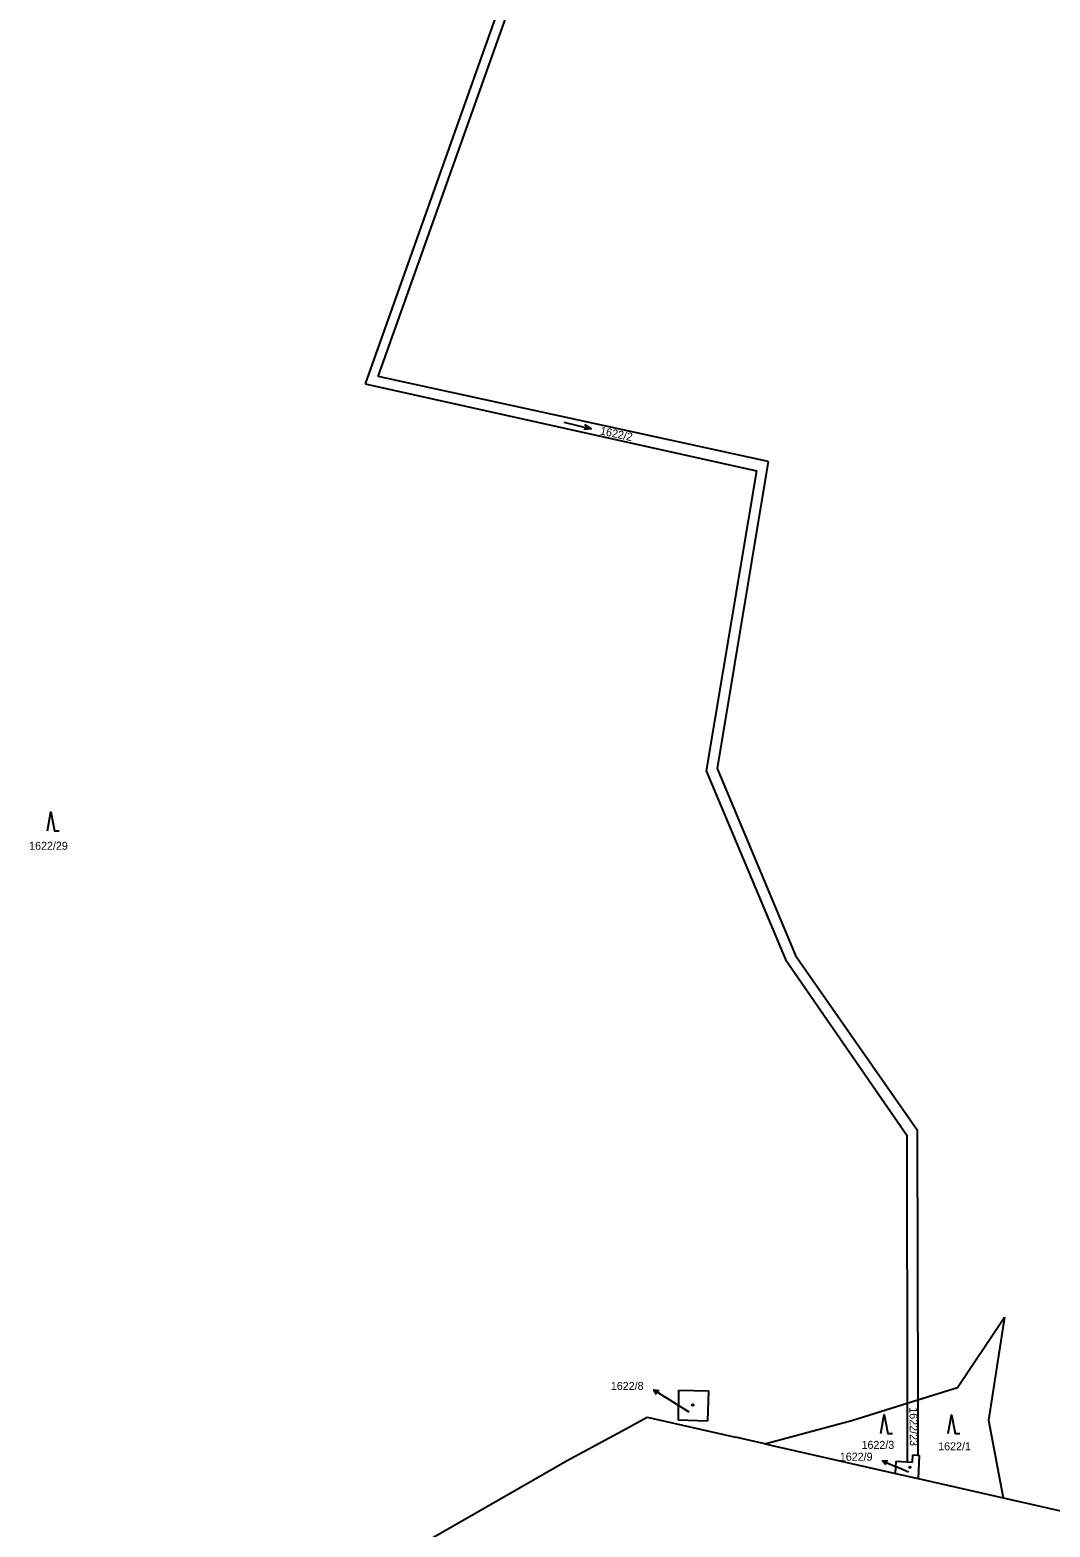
# Model space of a CAD drawing. Extents: x -763296 to -761805, y -1153670 to -1152034.
# Drawn here: x -762468.9 to -762252, y -1153393.1 to -1153075 of the extents above; entities that cross this region are included whole.
import ezdxf

# ---------------------------------------------------------------- set-up
doc = ezdxf.new("R2010")
doc.units = 0
for name, color, linetype in [('Vrstva 1', 7, 'Continuous'), ('Vrstva 13', 7, 'Continuous'), ('Vrstva 16', 7, 'Continuous'), ('Vrstva 18', 7, 'Continuous'), ('Vrstva 25', 7, 'Continuous'), ('Vrstva 6', 7, 'Continuous')]:
    doc.layers.add(name, color=color, linetype=linetype)

msp = doc.modelspace()

# ---------------------------------------------------------------- linework, layer by layer
at = {"layer": 'Vrstva 1'}
for p, q in [((-762394.86, -1153148.62), (-762335.11, -1152981.09)), ((-762337.96, -1152982.34), (-762397.62, -1153150.18)), ((-762311.93, -1153166.71), (-762394.86, -1153148.62)), ((-762397.62, -1153150.18), (-762314.43, -1153168.67)), ((-762314.43, -1153168.67), (-762325.12, -1153232.46)), ((-762311.93, -1153166.71), (-762322.73, -1153231.96)), ((-762325.12, -1153232.46), (-762308.2, -1153272.5)), ((-762322.73, -1153231.96), (-762306.1, -1153271.66)), ((-762308.2, -1153272.5), (-762282.45, -1153309.87)), ((-762306.1, -1153271.66), (-762280.28, -1153308.73)), ((-762280.28, -1153308.73), (-762280.11, -1153366.1)), ((-762282.45, -1153309.87), (-762282.37, -1153366.81)), ((-762331, -1153370.43), (-762330.92, -1153364.03)), ((-762330.92, -1153364.03), (-762324.62, -1153364.15)), ((-762324.62, -1153364.15), (-762324.79, -1153370.59)), ((-762280.11, -1153366.1), (-762280.07, -1153377.86)), ((-762282.37, -1153366.81), (-762282.35, -1153379.24)), ((-762324.79, -1153370.59), (-762331, -1153370.43)), ((-762284.82, -1153381.72), (-762284.69, -1153379.11)), ((-762284.69, -1153379.11), (-762282.35, -1153379.24)), ((-762281.24, -1153379.3), (-762281.16, -1153377.8)), ((-762281.16, -1153377.8), (-762280.07, -1153377.86)), ((-762280.07, -1153377.86), (-762279.8, -1153377.88)), ((-762279.8, -1153377.88), (-762280.06, -1153382.8)), ((-762282.35, -1153379.24), (-762281.24, -1153379.3))]:
    msp.add_line(p, q, dxfattribs=at)
at = {"layer": 'Vrstva 13'}
for p, q in [((-762354.76, -1153379.07), (-762342.97, -1153372.68)), ((-762342.97, -1153372.68), (-762337.61, -1153369.78)), ((-762337.61, -1153369.78), (-762318.87, -1153374.02)), ((-762312.65, -1153375.43), (-762318.87, -1153374.02)), ((-762312.65, -1153375.43), (-762284.82, -1153381.72)), ((-762361.78, -1153383.08), (-762354.76, -1153379.07)), ((-762284.82, -1153381.72), (-762280.06, -1153382.8)), ((-762384.53, -1153396.09), (-762361.78, -1153383.08)), ((-762280.06, -1153382.8), (-762261.96, -1153386.89)), ((-762261.96, -1153386.89), (-762236.33, -1153392.69))]:
    msp.add_line(p, q, dxfattribs=at)
at = {"layer": 'Vrstva 16'}
for p, q in [((-762336.237, -1153363.979), (-762333.7, -1153365.58)), ((-762328.73, -1153368.72), (-762333.7, -1153365.58)), ((-762287.598, -1153379.016), (-762284.85, -1153380.22)), ((-762282.12, -1153381.42), (-762284.85, -1153380.22))]:
    msp.add_line(p, q, dxfattribs=at)
for points in [[(-762335.658, -1153364.936), (-762336.237, -1153363.979), (-762335.125, -1153364.09)], [(-762286.883, -1153379.876), (-762287.598, -1153379.016), (-762286.481, -1153378.96)]]:
    msp.add_lwpolyline(points, dxfattribs=at)
at = {"layer": 'Vrstva 25'}
for points in [[(-762355.388, -1153158.374), (-762349.552, -1153159.766), (-762350.895, -1153158.932)], [(-762349.552, -1153159.766), (-762351.127, -1153159.904)], [(-762465.15, -1153245.18), (-762464.45, -1153241.18), (-762463.65, -1153245.18), (-762462.65, -1153245.18)], [(-762287.98, -1153373.23), (-762287.28, -1153369.23), (-762286.48, -1153373.23), (-762285.48, -1153373.23)], [(-762273.66, -1153373.26), (-762272.96, -1153369.26), (-762272.16, -1153373.26), (-762271.16, -1153373.26)]]:
    msp.add_lwpolyline(points, dxfattribs=at)
for centre in [(-762327.94, -1153367.17), (-762281.76, -1153380.44)]:
    msp.add_circle(centre, 0.175, dxfattribs=at)
at = {"layer": 'Vrstva 6'}
for p, q in [((-762271.7, -1153363.47), (-762261.71, -1153348.53)), ((-762261.71, -1153348.53), (-762265.09, -1153370.42)), ((-762282.37, -1153366.81), (-762280.11, -1153366.1)), ((-762280.11, -1153366.1), (-762271.7, -1153363.47)), ((-762293.92, -1153370.43), (-762282.37, -1153366.81)), ((-762312.65, -1153375.43), (-762293.92, -1153370.43)), ((-762265.09, -1153370.42), (-762261.96, -1153386.89))]:
    msp.add_line(p, q, dxfattribs=at)

# ---------------------------------------------------------------- texts
at = {"layer": 'Vrstva 16'}
for s, p in [('1622/8', (-762345.362, -1153363.98)), ('1622/9', (-762296.681, -1153379.02))]:
    msp.add_text(s, height=1.7, dxfattribs=at).set_placement(p)
at = {"layer": 'Vrstva 18'}
for s, rotation, p in [('1622/2', 347.95727, (-762347.757, -1153160.946)), ('1622/23', 270.72256, (-762281.89, -1153367.679))]:
    msp.add_text(s, height=1.7, rotation=rotation, dxfattribs=at).set_placement(p)
for s, height, p in [('1622/29', 1.7, (-762469.035, -1153249.21)), ('1622/8', 0.1, (-762328.962, -1153368.95)), ('1622/3', 1.7, (-762292.069, -1153376.5)), ('1622/1', 1.7, (-762275.774, -1153376.81)), ('1622/9', 0.1, (-762282.351, -1153381.42))]:
    msp.add_text(s, height=height, dxfattribs=at).set_placement(p)

doc.saveas('drawing.dxf')
